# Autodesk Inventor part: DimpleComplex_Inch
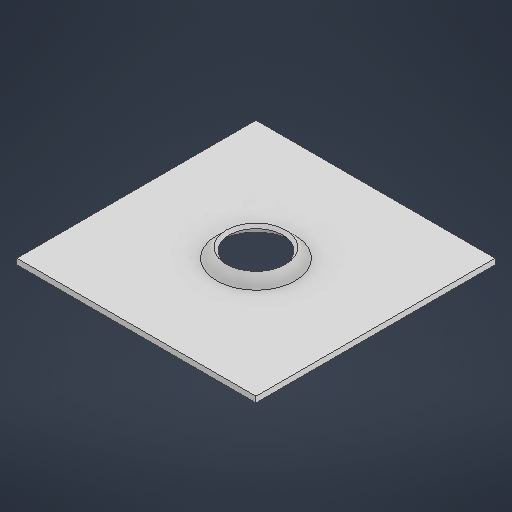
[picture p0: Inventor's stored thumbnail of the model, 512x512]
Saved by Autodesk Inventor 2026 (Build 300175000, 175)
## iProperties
Created: 2025-04
Part Number: DimpleComplex_Inch
Material: Generic
Document SubType Name: Sheet Metal
Designer: Autodesk, Inc
Density: 1 g/cm^3
Sheet Metal Rule: Default
Appearance: Default
Author: Autodesk, Inc
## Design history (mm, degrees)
node "Face1"
  sketch "Sketch1"
    geometry: L1 (-63.5, 63.5)-(63.5, 63.5); L2 (63.5, 63.5)-(63.5, -63.5); L3 (63.5, -63.5)-(-63.5, -63.5); L4 (-63.5, -63.5)-(-63.5, 63.5); L5 (-63.5, 63.5)-(63.5, -63.5); L6 (63.5, 63.5)-(-63.5, -63.5); 1 further point
    constraints: 12 end point, 2 midpoint, 2 parallel, 2 perpendicular, 1 horizontal
    dimensions: "d0" = 127 distance of L1.end L2.end
sketch "Sketch2"
  geometry: C1 r 12.7 at (0, 0); 2 further points
  constraints: 2 coincident, 1 centre point
  dimensions: "Diameter" = 25.4 diameter of C1
extrude "Extrusion1" join sketch "Sketch2" distance "d3" = 8.128 (= Thickness + Height); taper "d4" = 0 deg
workplane "Work Plane1"
sketch "Sketch3"
  geometry: C1 r 15.748 at (0, 0); C2 r 12.7 at (0, 0)
  constraints: 2 centre point, 1 coincident, 1 other
  dimensions: "d6" = 31.496 diameter of C1 (= Diameter + 2 x Thickness); "d7" = 25.4 diameter of C2 (= Diameter)
extrude "Extrusion2" join sketch "Sketch3" distance "d8" = 5.08 (= Height); taper "d9" = 45 deg (= Angle)
extrude "Extrusion3" cut sketch "Sketch3" distance "d10" = 8.128 (= Thickness + Height); taper "d11" = 45 deg (= Angle)
chamfer "Chamfer1" distance "d12" = 3.048 (= Thickness); stored, may be unused: second distance "d13" = 3.175, angle "d14" = 45 deg (= Angle)
fillet "Fillet1" dims "d15" = 3.302 (= fillet_radius)
body "Solid1"
face "Plate1" dims "d1" = 3.048 (= Thickness)
other parameters: "Thickness" = 3.048, "BendRadius" = 3.048 (= Thickness), "BendReliefWidth" = 3.048 (= Thickness), "BendReliefDepth" = 1.524 (= 0.5 x Thickness), "CornerReliefSize" = 12.192 (= 4 x Thickness), "SeamGap" = 0.00508, "MinimumRemnant" = 6.096 (= 2 x Thickness), "TransitionRadius" = 3.048 (= BendRadius), "JacobiRadiusSize" = 3.048 (= BendRadius), "GapSize" = 3.048 (= Thickness), "Height" = 5.08 [user parameter; used in 3 equation terms], "Angle" = 45 deg [user parameter; used in 3 equation terms], "fillet_radius" = 3.302 [user parameter; used in 1 equation term], "d5" = -3.048 (= -Thickness)
